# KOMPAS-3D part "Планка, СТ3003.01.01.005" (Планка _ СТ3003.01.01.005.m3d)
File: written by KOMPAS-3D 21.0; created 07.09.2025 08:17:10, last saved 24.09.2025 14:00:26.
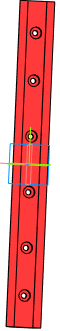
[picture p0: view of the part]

Document properties: Полное имя файла: C:\Users\1\Yandex.Disk\Документы\Новая папка\Стапель №2\Стапель _ СТ3003.00.00.000\Опора _ СТ3003.01.00.000\3D\Кронштейн _ СТ3003.01.01.000\Планка _ СТ3003.01.01.005.m3d

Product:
- Part/product: Планка  | designation СТ3003.01.01.005
    Материал: Сталь 45  ГОСТ 1050-2013 (density 7810 kg/m3)
    Масса: 1.670176
    Форматы листов документа: A3

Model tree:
1. Эскиз:1
2. Элемент выдавливания:1
     Расстояние 1 = 410
3. Эскиз:2  (with: Элемент выдавливания:1)
4. Элемент выдавливания:2
     Расстояние 2 = 14.4
5. Эскиз:3  (with: Элемент выдавливания:1, Элемент выдавливания:2)
6. Элемент выдавливания:4  (labels: Сталь 45  ГОСТ 1050-2013)
     Расстояние 2 = 8

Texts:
  СТ3003.01.01.005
